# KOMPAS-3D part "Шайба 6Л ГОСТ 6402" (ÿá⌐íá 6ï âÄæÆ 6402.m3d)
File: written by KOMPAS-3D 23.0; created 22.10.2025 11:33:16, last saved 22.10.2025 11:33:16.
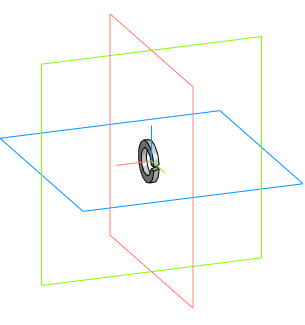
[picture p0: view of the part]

Document properties: Автор: ARM_513_VVK; Полное имя файла: F:\Демо\Демо вариант космос\Шайба 6Л ГОСТ 6402.m3d

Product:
- Part/product: Шайба 6Л ГОСТ 6402

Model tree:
1. Операция без истории:1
